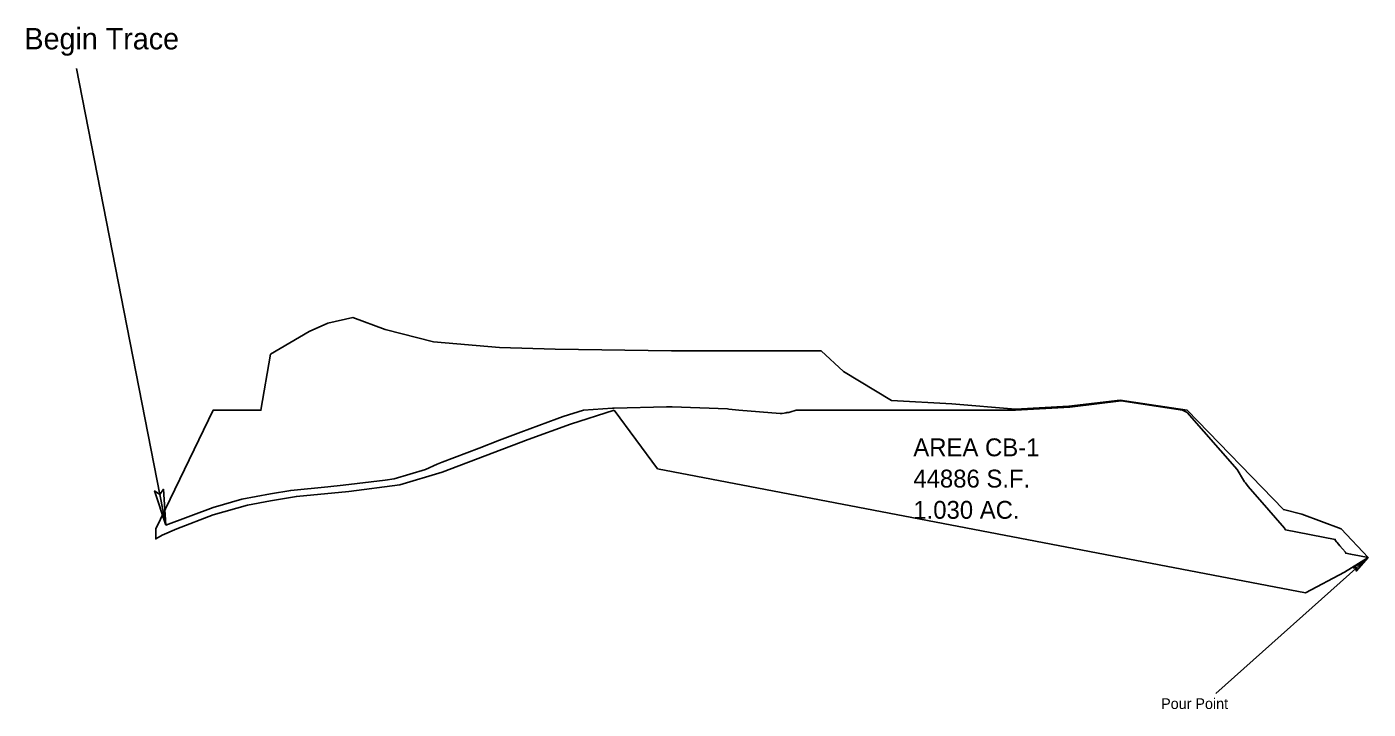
# Model space of a CAD drawing. Extents: x 2230 to 2981, y 3130 to 3512.
import ezdxf

# ---------------------------------------------------------------- set-up
doc = ezdxf.new("R2010")
doc.units = 0
for name, color, linetype in [('DESIGN - SCRATCH - User 1', 7, 'Continuous'), ('SURVEY - CENTERLINE - Preliminary', 7, 'Continuous'), ('SURVEY - CENTERLINE - Preliminary Text', 7, 'Continuous'), ('SURVEY - DRAINAGE - Area Shapes', 7, 'Continuous')]:
    doc.layers.add(name, color=color, linetype=linetype)

msp = doc.modelspace()

# ---------------------------------------------------------------- linework, layer by layer
at = {"layer": 'DESIGN - SCRATCH - User 1'}
msp.add_line((2980.81, 3214.91), (2895.61, 3138.81), dxfattribs=at)
msp.add_lwpolyline([(2980.81, 3214.91), (2974.15, 3207.28), (2974.29, 3209.08), (2972.45, 3209.18)], close=True, dxfattribs=at)
msp.add_lwpolyline([(2980.81, 3214.91), (2974.15, 3207.28), (2974.29, 3209.08), (2972.45, 3209.18), (2980.81, 3214.91)], dxfattribs=at)
at = {"layer": 'SURVEY - CENTERLINE - Preliminary'}
msp.add_lwpolyline([(2307.8, 3232.91), (2334.24, 3242.95), (2350.34, 3247.53), (2366.31, 3250.5), (2377.69, 3252.43), (2398.39, 3254.51), (2406.98, 3255.31), (2430.47, 3258.28), (2435.54, 3258.94), (2453.07, 3264.19), (2459.62, 3267.22), (2462.54, 3268.3), (2483.11, 3276.1), (2494.62, 3280.53), (2506.53, 3285.06), (2526.7, 3292.55), (2530.17, 3293.79), (2541.52, 3297.38), (2557.72, 3298.47), (2558.77, 3298.49), (2588.02, 3299.19), (2589.03, 3299.26), (2589.08, 3299.27), (2590.85, 3299.2), (2591.14, 3299.19), (2622.21, 3298.12), (2622.93, 3298.04), (2628.44, 3297.38), (2651.58, 3295.54), (2652.7, 3295.47), (2652.74, 3295.46), (2653.99, 3295.73), (2654.79, 3295.91), (2655.01, 3295.94), (2655.49, 3296.01), (2656.23, 3296.12), (2656.56, 3296.16), (2656.99, 3296.23), (2660.62, 3297.38), (2687.08, 3297.38), (2719.16, 3297.38), (2751.24, 3297.38), (2783.31, 3297.38), (2813.75, 3299.08), (2815.39, 3299.26), (2842.46, 3302.56), (2847.47, 3301.94), (2876.83, 3297.38), (2879.54, 3296), (2907.44, 3264.19), (2910.96, 3258.24), (2911.62, 3257.33), (2912.06, 3256.74), (2913.68, 3254.69), (2916.09, 3251.91), (2920.11, 3247.27), (2933.91, 3231.34), (2934.13, 3231.01), (2934.58, 3230.34), (2934.57, 3230.31), (2934.57, 3230.29), (2962.38, 3225.01), (2962.32, 3224.55), (2963.15, 3223.58), (2963.37, 3223.34), (2965.01, 3221.42), (2966.47, 3219.73), (2968.08, 3217.85), (2968.16, 3217.63), (2968.28, 3217.31), (2968.28, 3217.31), (2968.28, 3217.3), (2970.99, 3216.79), (2975.9, 3215.85), (2980.81, 3214.91), (2980.81, 3214.91)], dxfattribs=at)
at = {"layer": 'SURVEY - CENTERLINE - Preliminary Text'}
msp.add_line((2307.8, 3232.91), (2257.78, 3488.67), dxfattribs=at)
msp.add_lwpolyline([(2307.8, 3232.91), (2301.49, 3252.16), (2304.44, 3250.09), (2306.5, 3253.14)], close=True, dxfattribs=at)
msp.add_lwpolyline([(2307.8, 3232.91), (2301.49, 3252.16), (2304.44, 3250.09), (2306.5, 3253.14), (2307.8, 3232.91)], dxfattribs=at)
at = {"layer": 'SURVEY - DRAINAGE - Area Shapes'}
msp.add_line((2583.06, 3264.55), (2945.71, 3195.15), dxfattribs=at)
for points in [[(2945.71, 3195.15), (2967.61, 3206.63), (2980.81, 3214.91), (2965.75, 3231.01), (2943.7, 3239.24), (2933.36, 3241.7), (2879.54, 3297.38), (2842, 3303.04), (2813.28, 3299.57), (2783.31, 3297.89), (2747.78, 3300.96), (2713.92, 3302.8), (2687.08, 3319.11), (2674.6, 3330.57), (2590.85, 3330.57), (2525.7, 3331.6), (2494.62, 3332.53), (2457.61, 3335.67), (2430.47, 3342.63), (2412.43, 3349.23), (2398.39, 3346.04), (2387.94, 3341.38), (2366.31, 3328.7), (2361.05, 3297.38), (2334.24, 3297.38), (2302.16, 3231.01), (2302.16, 3225.28), (2305.68, 3227.37), (2313.86, 3231.01), (2334.24, 3238.75), (2353.54, 3244.23), (2366.31, 3246.61), (2380.92, 3249.08), (2410.24, 3251.93), (2438.79, 3255.58), (2462.54, 3262.7), (2510.53, 3280.92), (2534.22, 3289.6), (2558.77, 3297.38)], [(2558.77, 3297.38), (2583.06, 3264.55)]]:
    msp.add_lwpolyline(points, dxfattribs=at)

# ---------------------------------------------------------------- texts
at = {"layer": 'DESIGN - SCRATCH - User 1'}
msp.add_text('Pour Point', height=6, dxfattribs=at).set_placement((2864.93, 3130.04))
at = {"layer": 'SURVEY - CENTERLINE - Preliminary Text'}
msp.add_text('Begin Trace', height=12, dxfattribs=at).set_placement((2228.65, 3499.41))
at = {"layer": 'SURVEY - DRAINAGE - Area Shapes'}
for s, p in [('AREA CB-1', (2726.21, 3271.57)), ('44886 S.F.', (2726.21, 3254.07)), ('1.030 AC.', (2726.21, 3236.57))]:
    msp.add_text(s, height=10, dxfattribs=at).set_placement(p)

doc.saveas('drawing.dxf')
